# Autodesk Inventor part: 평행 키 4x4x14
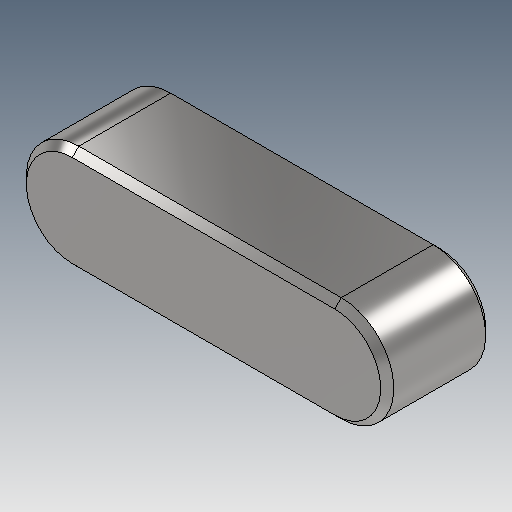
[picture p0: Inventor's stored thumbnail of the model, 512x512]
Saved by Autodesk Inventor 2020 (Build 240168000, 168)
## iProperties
Created: 2024-12
Part Number: 평행 키 4x4x14
Material: 강철, 연강
Description: 키 및 해당 키홈
Document SubType Name: Modeling
Designer: shin
Density: 7.85 g/cm^3
Appearance: 기본값
Author: jhkim
Sending System: Autodesk Inventor 2025
Preprocessor: ST-DEVELOPER v20
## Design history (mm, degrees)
feature "Solid1"
node "솔리드1"
